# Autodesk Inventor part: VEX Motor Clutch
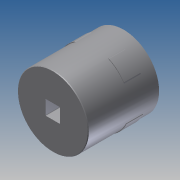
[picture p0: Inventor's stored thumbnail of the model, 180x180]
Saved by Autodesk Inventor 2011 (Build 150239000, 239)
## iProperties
Created: 2010-06
Part Number: VEX Motor Clutch
Document SubType Name: Modeling
Designer: Phil
Density: 1 g/cm^3
Author: Phil
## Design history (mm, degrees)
sketch "Sketch1"
  geometry: C1 r 7.747 at (0, 0); 1 further point
  constraints: 1 centre point, 1 coincident
  dimensions: "d0" = 15.494 diameter of C1
extrude "Extrusion1" new body sketch "Sketch1" distance "d1" = 15.494; taper "d2" = 0 deg
chamfer "Chamfer1" distance "d3" = 0.127; stored, may be unused: second distance "d4" = 3.175, angle "d5" = 45 deg
sketch "Sketch2"
  geometry: L1 (-1.588, -1.461)-(-1.588, 1.46); L2 (-1.461, 1.587)-(1.46, 1.587); L3 (1.46, -1.588)-(-1.461, -1.588); L4 (1.587, 1.46)-(1.587, -1.461); A1 r 0.127 centre (-1.461, 1.46) between (-1.461, 1.587) and (-1.588, 1.46); A2 r 0.127 centre (-1.461, -1.461) between (-1.588, -1.461) and (-1.461, -1.588); A3 r 0.127 centre (1.46, 1.46) between (1.587, 1.46) and (1.46, 1.587); A4 r 0.127 centre (1.46, -1.461) between (1.46, -1.588) and (1.587, -1.461); 18 further points
  constraints: 8 end point, 8 point on circle, 4 centre point
extrude "Extrusion2" cut sketch "Sketch2" distance "d6" = 5.08; taper "d7" = 0 deg
sketch "Sketch3"
  geometry: C1 r 7.747 at (0, 0) reference; C2 r 3.683 at (0, 0)
  constraints: 1 centre point, 1 coincident
  dimensions: "d8" = 7.366 diameter of C2
extrude "Extrusion3" join sketch "Sketch3" distance "d9" = 0.762; taper "d10" = 0 deg
chamfer "Chamfer2" distance "d11" = 0.508; stored, may be unused: second distance "d12" = 0.7366, angle "d13" = 45 deg
sketch "Sketch4"
  geometry: L1 (-1.461, 1.587)-(1.46, 1.587); L2 (1.587, 1.46)-(1.587, -1.461); L3 (1.46, -1.588)-(-1.461, -1.588); L4 (-1.588, -1.461)-(-1.588, 1.46); A1 r 0.127 centre (1.46, 1.46) between (1.587, 1.46) and (1.46, 1.587); A2 r 0.127 centre (1.46, -1.461) between (1.46, -1.588) and (1.587, -1.461); A3 r 0.127 centre (-1.461, -1.461) between (-1.588, -1.461) and (-1.461, -1.588); A4 r 0.127 centre (-1.461, 1.46) between (-1.461, 1.587) and (-1.588, 1.46)
  constraints: 8 end point, 8 point on circle, 4 centre point
extrude "Extrusion4" cut sketch "Sketch4" distance "d14" = 6.35; taper "d15" = 0 deg
workplane "Work Plane1"
sketch "Sketch5"
  geometry: L1 (6.604, -4.25)-(6.604, -4.05); L2 (-1.46, -1.588)-(1.461, -1.588) reference; L3 (1.588, -1.461)-(1.588, 1.46) reference; L4 (1.461, 1.587)-(-1.46, 1.587) reference; L5 (-1.587, 1.46)-(-1.587, -1.461) reference; C1 r 7.62 at (0, 0) reference; C2 r 7.747 at (0, 0) reference; C3 r 7.747 at (0, 0) reference; A1 r 7.874 centre (0, 0) between (3.344, -7.128) and (6.583, -4.32); A2 r 0.127 centre (3.29, -7.014) between (3.175, -7.066) and (3.344, -7.128); A3 r 0.127 centre (6.477, -4.25) between (6.583, -4.32) and (6.604, -4.25); A4 r 0.127 centre (1.461, -1.461) between (1.461, -1.588) and (1.588, -1.461) reference; A5 r 0.127 centre (1.461, 1.46) between (1.588, 1.46) and (1.461, 1.587) reference; A6 r 0.127 centre (-1.46, 1.46) between (-1.46, 1.587) and (-1.587, 1.46) reference; A7 r 0.127 centre (-1.46, -1.461) between (-1.587, -1.461) and (-1.46, -1.588) reference; A8 r 7.747 centre (0, 0) between (3.175, -7.066) and (6.604, -4.05); 2 further points
  constraints: 8 point on circle, 4 centre point, 2 end point
extrude "Extrusion5" join sketch "Sketch5" distance "d17" = 3.6068; taper "d18" = 0 deg
pattern_circular "Circular Pattern1" dims angle "d20" = 360 deg
body "Solid1"
node "Projected Loop1"
node "Projected Loop2"
other parameters: "d16" = -2.921
